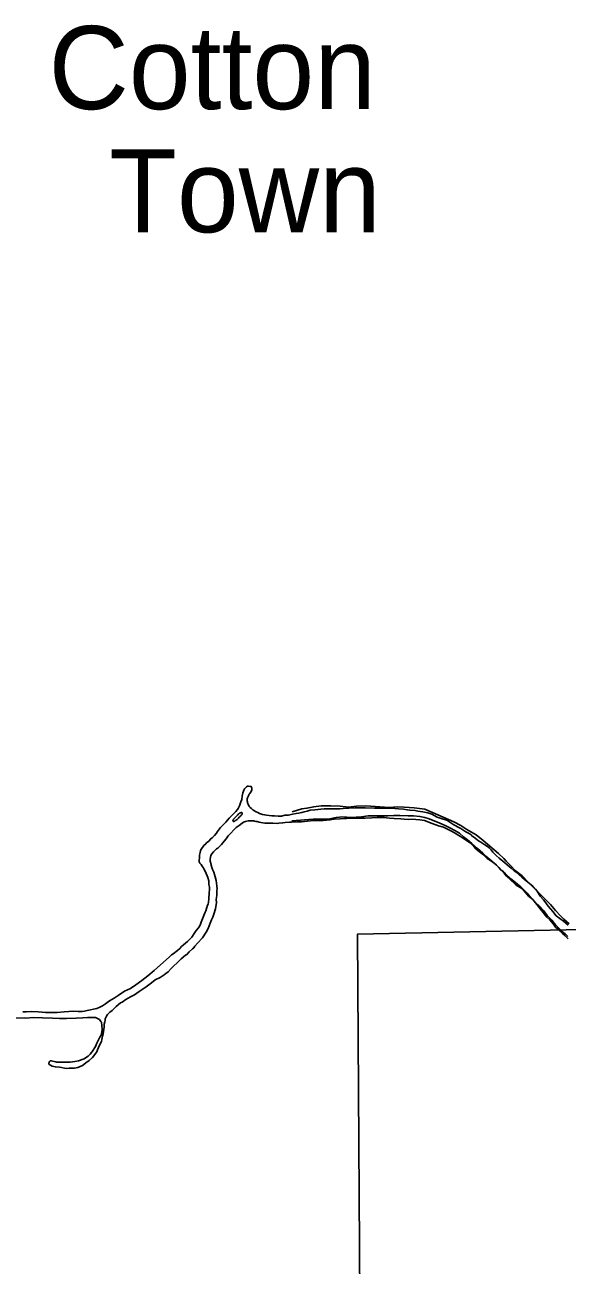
# Model space of a CAD drawing. Extents: x 1374139 to 1377472, y 1168351 to 1170484.
# Drawn here: x 1374645 to 1374679.5, y 1169664.8 to 1169743.6 of the extents above; entities that cross this region are included whole.
import ezdxf

# ---------------------------------------------------------------- set-up
doc = ezdxf.new("R2010")
doc.units = 0
doc.layers.add('Default', color=7, linetype='Continuous')

msp = doc.modelspace()

# ---------------------------------------------------------------- linework, layer by layer
at = {"layer": 'Default'}
for points in [[(1374672.64, 1169692.591), (1374672.281, 1169692.782), (1374672.151, 1169692.862), (1374671.832, 1169693.073), (1374671.602, 1169693.144), (1374671.233, 1169693.275), (1374670.894, 1169693.466), (1374670.634, 1169693.537), (1374670.425, 1169693.587), (1374670.315, 1169693.607), (1374670.006, 1169693.648), (1374669.836, 1169693.689), (1374669.496, 1169693.709), (1374669.327, 1169693.74), (1374669.097, 1169693.77), (1374668.778, 1169693.811), (1374668.528, 1169693.821), (1374668.248, 1169693.842), (1374667.849, 1169693.853), (1374667.24, 1169693.834), (1374666.661, 1169693.875), (1374666.002, 1169693.857), (1374665.253, 1169693.818), (1374665.043, 1169693.808), (1374664.763, 1169693.799), (1374664.294, 1169693.81), (1374664.044, 1169693.8), (1374663.834, 1169693.771), (1374663.455, 1169693.732), (1374663.165, 1169693.712), (1374662.965, 1169693.652), (1374662.785, 1169693.603), (1374662.626, 1169693.573), (1374662.416, 1169693.523), (1374662.266, 1169693.494), (1374662.026, 1169693.454), (1374661.776, 1169693.404), (1374661.557, 1169693.395), (1374661.337, 1169693.335), (1374661.117, 1169693.336), (1374660.888, 1169693.346), (1374660.718, 1169693.366), (1374660.388, 1169693.397), (1374660.259, 1169693.427), (1374660.129, 1169693.438), (1374659.929, 1169693.498), (1374659.829, 1169693.569), (1374659.72, 1169693.609), (1374659.57, 1169693.699), (1374659.52, 1169693.739), (1374659.421, 1169693.82), (1374659.351, 1169693.88), (1374659.291, 1169693.94), (1374659.281, 1169693.96), (1374659.241, 1169694.041), (1374659.221, 1169694.101), (1374659.172, 1169694.181), (1374659.172, 1169694.241), (1374659.162, 1169694.301), (1374659.162, 1169694.341), (1374659.152, 1169694.411), (1374659.162, 1169694.441), (1374659.172, 1169694.491), (1374659.192, 1169694.552), (1374659.213, 1169694.592), (1374659.233, 1169694.632), (1374659.263, 1169694.682), (1374659.293, 1169694.732), (1374659.323, 1169694.782), (1374659.363, 1169694.842), (1374659.403, 1169694.912), (1374659.453, 1169695.012), (1374659.453, 1169695.042), (1374659.453, 1169695.062), (1374659.443, 1169695.102), (1374659.443, 1169695.112), (1374659.423, 1169695.152), (1374659.414, 1169695.212), (1374659.234, 1169695.233), (1374659.184, 1169695.233), (1374659.114, 1169695.193), (1374659.074, 1169695.153), (1374659.024, 1169695.113), (1374658.994, 1169695.073), (1374658.954, 1169694.993), (1374658.924, 1169694.933), (1374658.873, 1169694.823), (1374658.843, 1169694.612), (1374658.813, 1169694.402), (1374658.752, 1169694.242), (1374658.712, 1169694.112), (1374658.672, 1169694.002), (1374658.592, 1169693.832), (1374658.532, 1169693.751), (1374658.442, 1169693.641), (1374658.311, 1169693.502), (1374658.191, 1169693.372), (1374658.022, 1169693.21)], [(1374662.015, 1169693.618), (1374662.634, 1169693.799), (1374662.954, 1169693.84), (1374663.383, 1169693.93), (1374663.853, 1169694.001), (1374664.472, 1169693.991), (1374665.061, 1169693.961), (1374665.6, 1169693.902), (1374666.11, 1169693.972), (1374666.689, 1169693.983), (1374667.578, 1169693.933), (1374668.187, 1169693.894), (1374668.696, 1169693.924), (1374669.126, 1169693.915), (1374669.755, 1169693.865), (1374670.434, 1169693.786), (1374671.273, 1169693.426), (1374672.282, 1169692.976), (1374672.722, 1169692.736), (1374673.112, 1169692.485), (1374673.701, 1169692.155), (1374674.151, 1169691.795), (1374674.431, 1169691.565), (1374674.841, 1169691.195), (1374675.121, 1169690.965), (1374675.46, 1169690.654), (1374675.6, 1169690.484), (1374675.9, 1169690.184), (1374676.19, 1169689.884), (1374676.62, 1169689.533), (1374677.03, 1169689.123), (1374677.26, 1169688.883), (1374677.599, 1169688.542), (1374677.809, 1169688.342), (1374678.179, 1169687.982), (1374678.429, 1169687.722), (1374678.739, 1169687.331), (1374679.059, 1169686.991), (1374679.269, 1169686.791), (1374679.619, 1169686.501)], [(1374659.614, 1169693.017), (1374659.569, 1169693.028), (1374659.479, 1169693.038), (1374659.349, 1169693.039), (1374659.229, 1169693.039), (1374659.059, 1169692.999), (1374658.929, 1169692.959), (1374658.829, 1169692.889), (1374658.639, 1169692.74), (1374658.449, 1169692.62), (1374658.319, 1169692.46), (1374658.119, 1169692.26), (1374657.939, 1169692.09), (1374657.819, 1169691.9), (1374657.698, 1169691.74), (1374657.528, 1169691.54), (1374657.288, 1169691.31), (1374657.208, 1169691.26), (1374657.088, 1169691.13), (1374657.008, 1169691.06), (1374656.918, 1169690.95), (1374656.918, 1169690.94), (1374656.857, 1169690.839)], [(1374658.022, 1169693.21), (1374657.794, 1169692.953), (1374657.518, 1169692.669)], [(1374658.499, 1169693.365), (1374658.457, 1169693.323), (1374658.426, 1169693.287), (1374658.387, 1169693.247), (1374658.349, 1169693.207), (1374658.328, 1169693.184), (1374658.318, 1169693.167), (1374658.292, 1169693.142), (1374658.284, 1169693.126), (1374658.27, 1169693.092), (1374658.259, 1169693.076), (1374658.252, 1169693.061), (1374658.25, 1169693.046), (1374658.251, 1169693.03), (1374658.258, 1169693.017), (1374658.271, 1169693.004), (1374658.288, 1169692.998), (1374658.305, 1169693), (1374658.327, 1169693.006), (1374658.353, 1169693.017), (1374658.378, 1169693.036), (1374658.4, 1169693.051), (1374658.428, 1169693.07), (1374658.455, 1169693.088), (1374658.48, 1169693.108), (1374658.512, 1169693.123), (1374658.54, 1169693.142), (1374658.565, 1169693.164), (1374658.594, 1169693.194), (1374658.615, 1169693.216), (1374658.634, 1169693.241), (1374658.656, 1169693.264), (1374658.688, 1169693.299), (1374658.721, 1169693.334), (1374658.743, 1169693.361), (1374658.768, 1169693.391), (1374658.793, 1169693.414), (1374658.815, 1169693.434), (1374658.829, 1169693.45), (1374658.839, 1169693.467), (1374658.846, 1169693.485), (1374658.847, 1169693.505), (1374658.842, 1169693.528), (1374658.832, 1169693.551), (1374658.815, 1169693.568), (1374658.796, 1169693.574), (1374658.774, 1169693.574), (1374658.751, 1169693.567), (1374658.723, 1169693.552)], [(1374658.723, 1169693.552), (1374658.673, 1169693.522), (1374658.637, 1169693.496), (1374658.596, 1169693.463), (1374658.562, 1169693.433), (1374658.539, 1169693.407), (1374658.518, 1169693.386), (1374658.499, 1169693.365)], [(1374660.386, 1169692.896), (1374660.28, 1169692.898), (1374660.147, 1169692.916), (1374660.029, 1169692.934), (1374659.921, 1169692.961), (1374659.788, 1169692.988), (1374659.697, 1169693.003), (1374659.614, 1169693.017)], [(1374665.472, 1169693.195), (1374665.341, 1169693.187), (1374665.071, 1169693.167), (1374664.672, 1169693.148), (1374664.412, 1169693.098), (1374663.973, 1169693.069), (1374663.393, 1169693.06), (1374663.184, 1169693.041), (1374662.614, 1169692.982), (1374662.325, 1169692.982), (1374661.975, 1169692.953), (1374661.845, 1169692.943), (1374661.576, 1169692.934), (1374661.406, 1169692.904), (1374661.176, 1169692.885), (1374661.056, 1169692.875), (1374660.777, 1169692.895), (1374660.487, 1169692.896), (1374660.386, 1169692.896)], [(1374661.996, 1169693.037), (1374663.354, 1169693.149), (1374664.303, 1169693.139), (1374664.812, 1169693.25), (1374665.241, 1169693.29), (1374665.771, 1169693.251), (1374666.09, 1169693.261), (1374666.42, 1169693.301), (1374666.839, 1169693.352), (1374667.329, 1169693.362), (1374667.648, 1169693.363), (1374668.098, 1169693.363), (1374668.477, 1169693.373), (1374668.847, 1169693.384), (1374669.386, 1169693.364), (1374669.715, 1169693.354), (1374670.125, 1169693.314), (1374670.445, 1169693.255), (1374670.724, 1169693.155), (1374670.974, 1169693.055), (1374671.344, 1169692.905), (1374671.773, 1169692.715), (1374672.023, 1169692.585), (1374672.343, 1169692.425), (1374672.653, 1169692.245), (1374672.902, 1169692.025), (1374673.162, 1169691.824), (1374673.432, 1169691.604), (1374673.782, 1169691.274), (1374674.122, 1169690.974), (1374674.322, 1169690.794), (1374674.572, 1169690.583), (1374674.971, 1169690.233), (1374675.231, 1169689.973), (1374675.571, 1169689.673), (1374675.911, 1169689.352), (1374676.091, 1169689.212), (1374676.331, 1169689.022), (1374676.55, 1169688.852), (1374676.95, 1169688.432), (1374677.22, 1169688.111), (1374677.47, 1169687.851), (1374677.72, 1169687.611), (1374677.97, 1169687.331), (1374678.22, 1169687.02), (1374678.51, 1169686.73), (1374678.74, 1169686.42), (1374679.19, 1169685.979), (1374679.349, 1169685.849), (1374679.529, 1169685.679)], [(1374665.472, 1169693.195), (1374666.092, 1169693.21), (1374666.644, 1169693.199), (1374667.084, 1169693.221), (1374667.404, 1169693.248), (1374667.654, 1169693.259), (1374667.867, 1169693.243)], [(1374676.147, 1169689.058), (1374675.629, 1169689.52), (1374675.529, 1169689.64), (1374675.42, 1169689.811), (1374675.28, 1169689.921), (1374675.141, 1169690.082), (1374675.001, 1169690.222), (1374674.842, 1169690.343), (1374674.603, 1169690.513), (1374674.403, 1169690.654), (1374674.164, 1169690.875), (1374674.094, 1169690.935), (1374673.915, 1169691.066), (1374673.685, 1169691.267), (1374673.556, 1169691.407), (1374673.327, 1169691.638), (1374672.968, 1169691.869), (1374672.698, 1169692.04), (1374672.329, 1169692.281), (1374672.13, 1169692.372), (1374671.621, 1169692.633), (1374671.302, 1169692.724), (1374670.913, 1169692.865), (1374670.424, 1169693.056), (1374670.114, 1169693.097), (1374669.865, 1169693.128), (1374669.685, 1169693.138), (1374669.435, 1169693.128), (1374669.136, 1169693.139), (1374668.926, 1169693.159), (1374668.497, 1169693.18), (1374668.197, 1169693.211), (1374667.997, 1169693.231), (1374667.867, 1169693.243)], [(1374657.518, 1169692.669), (1374657.471, 1169692.622), (1374657.331, 1169692.442), (1374657.27, 1169692.352), (1374657.2, 1169692.252), (1374657.08, 1169692.112), (1374656.94, 1169691.962), (1374656.84, 1169691.902), (1374656.71, 1169691.752), (1374656.58, 1169691.632), (1374656.52, 1169691.582), (1374656.41, 1169691.472), (1374656.31, 1169691.342), (1374656.239, 1169691.232), (1374656.199, 1169691.122), (1374656.179, 1169691.032), (1374656.129, 1169690.851), (1374656.129, 1169690.771), (1374656.118, 1169690.641), (1374656.098, 1169690.561), (1374656.088, 1169690.521), (1374656.098, 1169690.481), (1374656.098, 1169690.441), (1374656.148, 1169690.35), (1374656.227, 1169690.26), (1374656.297, 1169690.16), (1374656.357, 1169690.08), (1374656.406, 1169689.979), (1374656.486, 1169689.829), (1374656.615, 1169689.548), (1374656.665, 1169689.428), (1374656.714, 1169689.217), (1374656.724, 1169688.997), (1374656.754, 1169688.817), (1374656.753, 1169688.636), (1374656.743, 1169688.496), (1374656.743, 1169688.356), (1374656.722, 1169688.216), (1374656.722, 1169688.085), (1374656.702, 1169687.875), (1374656.671, 1169687.735), (1374656.641, 1169687.685), (1374656.521, 1169687.314), (1374656.49, 1169687.234), (1374656.41, 1169687.024), (1374656.36, 1169686.914), (1374656.239, 1169686.604), (1374656.169, 1169686.404), (1374656.069, 1169686.244), (1374655.919, 1169686.074), (1374655.829, 1169685.943), (1374655.638, 1169685.653), (1374655.518, 1169685.523), (1374655.368, 1169685.363), (1374655.118, 1169685.154), (1374654.978, 1169685.044), (1374654.868, 1169684.924), (1374654.728, 1169684.804), (1374654.448, 1169684.594), (1374654.358, 1169684.514), (1374654.238, 1169684.414), (1374654.227, 1169684.384)], [(1374679.537, 1169686.406), (1374679.248, 1169686.657), (1374678.789, 1169686.999), (1374678.57, 1169687.27), (1374678.281, 1169687.621), (1374678.062, 1169687.912), (1374677.983, 1169688.022), (1374677.763, 1169688.253), (1374677.574, 1169688.574), (1374677.475, 1169688.694), (1374677.295, 1169688.895), (1374677.096, 1169689.056), (1374676.887, 1169689.217), (1374676.607, 1169689.458), (1374676.239, 1169689.769), (1374676.109, 1169689.869), (1374675.93, 1169690.02), (1374675.81, 1169690.12), (1374675.531, 1169690.361), (1374675.401, 1169690.472), (1374675.162, 1169690.673), (1374674.983, 1169690.843), (1374674.763, 1169691.054), (1374674.654, 1169691.205), (1374674.524, 1169691.315), (1374674.425, 1169691.415), (1374674.255, 1169691.506), (1374673.996, 1169691.687), (1374673.846, 1169691.777), (1374673.737, 1169691.858), (1374673.527, 1169692.018), (1374673.457, 1169692.058), (1374673.378, 1169692.149), (1374673.258, 1169692.239), (1374673.039, 1169692.34), (1374672.909, 1169692.42), (1374672.739, 1169692.551), (1374672.64, 1169692.591)], [(1374656.857, 1169690.839), (1374656.829, 1169690.739), (1374656.799, 1169690.601), (1374656.81, 1169690.479), (1374656.86, 1169690.258)], [(1374656.86, 1169690.258), (1374656.876, 1169690.229), (1374656.916, 1169690.078), (1374656.976, 1169689.908), (1374657.035, 1169689.768), (1374657.114, 1169689.477), (1374657.187, 1169689.244)], [(1374657.187, 1169689.244), (1374657.217, 1169689.078), (1374657.228, 1169688.91), (1374657.241, 1169688.723)], [(1374657.241, 1169688.723), (1374657.232, 1169688.635), (1374657.232, 1169688.575), (1374657.222, 1169688.285), (1374657.181, 1169688.044), (1374657.201, 1169687.844), (1374657.15, 1169687.453), (1374657.039, 1169687.103), (1374656.969, 1169686.913), (1374656.899, 1169686.743), (1374656.809, 1169686.533), (1374656.668, 1169686.202), (1374656.548, 1169685.972), (1374656.327, 1169685.592), (1374656.007, 1169685.262), (1374655.827, 1169685.072), (1374655.757, 1169684.972), (1374655.687, 1169684.892), (1374655.476, 1169684.702), (1374655.326, 1169684.542), (1374655.246, 1169684.502), (1374654.956, 1169684.262), (1374654.856, 1169684.162), (1374654.336, 1169683.653), (1374654.136, 1169683.443), (1374653.996, 1169683.333), (1374653.885, 1169683.243), (1374653.626, 1169683.083), (1374653.306, 1169682.923), (1374653.076, 1169682.733), (1374652.735, 1169682.484), (1374652.475, 1169682.314), (1374652.295, 1169682.184), (1374651.995, 1169681.974), (1374651.735, 1169681.855), (1374651.455, 1169681.685), (1374651.205, 1169681.515), (1374651.115, 1169681.465), (1374650.835, 1169681.245), (1374650.655, 1169681.076), (1374650.575, 1169680.976), (1374650.425, 1169680.866), (1374650.285, 1169680.726), (1374650.225, 1169680.616), (1374650.145, 1169680.455), (1374650.145, 1169680.425), (1374650.128, 1169680.353)], [(1374677.388, 1169687.94), (1374677.303, 1169688.034), (1374677.024, 1169688.255), (1374676.925, 1169688.385), (1374676.845, 1169688.475), (1374676.696, 1169688.646), (1374676.626, 1169688.726), (1374676.536, 1169688.787), (1374676.317, 1169688.917), (1374676.197, 1169688.988), (1374676.147, 1169689.058)], [(1374677.388, 1169687.94), (1374677.781, 1169687.42), (1374678.186, 1169686.925)], [(1374679.555, 1169685.535), (1374679.326, 1169685.756), (1374679.186, 1169685.886), (1374679.027, 1169686.047), (1374678.748, 1169686.278), (1374678.608, 1169686.468), (1374678.389, 1169686.739), (1374678.186, 1169686.925)], [(1374700.109, 1169686.03), (1374692.682, 1169686.381), (1374666.167, 1169685.836), (1374666.331, 1169659.315), (1374639.748, 1169659.329), (1374639.928, 1169632.938), (1374613.437, 1169632.866), (1374613.711, 1169606.658), (1374612.681, 1169606.654), (1374587.094, 1169606.782), (1374586.375, 1169606.748), (1374586.378, 1169604.285)], [(1374654.227, 1169684.384), (1374653.257, 1169683.524), (1374652.837, 1169683.185), (1374652.457, 1169682.895), (1374652.087, 1169682.605), (1374651.737, 1169682.386), (1374651.367, 1169682.206), (1374650.957, 1169681.936), (1374650.697, 1169681.757), (1374650.407, 1169681.587), (1374650.147, 1169681.407), (1374649.967, 1169681.287), (1374649.787, 1169681.197), (1374649.597, 1169681.108), (1374648.997, 1169680.989), (1374648.828, 1169680.949), (1374648.668, 1169680.929), (1374648.428, 1169680.92), (1374648.128, 1169680.93), (1374647.539, 1169680.891), (1374647.09, 1169680.852), (1374646.68, 1169680.863), (1374646.341, 1169680.854), (1374646.141, 1169680.884), (1374645.872, 1169680.905), (1374645.432, 1169680.926), (1374645.113, 1169680.906), (1374644.903, 1169680.897)], [(1374649.224, 1169680.537), (1374649.016, 1169680.538), (1374648.707, 1169680.518), (1374648.297, 1169680.499), (1374647.678, 1169680.47), (1374647.239, 1169680.481), (1374646.789, 1169680.492), (1374646.15, 1169680.514), (1374645.581, 1169680.535), (1374645.092, 1169680.496), (1374644.463, 1169680.517), (1374644.063, 1169680.508), (1374643.584, 1169680.499), (1374643.045, 1169680.49), (1374642.685, 1169680.451), (1374642.002, 1169680.409)], [(1374649.224, 1169680.537), (1374649.321, 1169680.534), (1374649.446, 1169680.539), (1374649.517, 1169680.529), (1374649.598, 1169680.504), (1374649.688, 1169680.463), (1374649.766, 1169680.412), (1374649.818, 1169680.349), (1374649.867, 1169680.284), (1374649.907, 1169680.246)], [(1374649.602, 1169678.914), (1374649.662, 1169679.024), (1374649.702, 1169679.114), (1374649.803, 1169679.284), (1374649.883, 1169679.424), (1374649.933, 1169679.634), (1374649.943, 1169679.785), (1374649.924, 1169680.025), (1374649.907, 1169680.246)], [(1374650.128, 1169680.353), (1374650.11, 1169680.267), (1374650.08, 1169680.117), (1374650.064, 1169679.946), (1374650.055, 1169679.781), (1374650.028, 1169679.637), (1374650.007, 1169679.499), (1374649.966, 1169679.355), (1374649.939, 1169679.249), (1374649.92, 1169679.138), (1374649.893, 1169679.01), (1374649.833, 1169678.896)], [(1374649.833, 1169678.896), (1374649.701, 1169678.633), (1374649.641, 1169678.483), (1374649.601, 1169678.363), (1374649.34, 1169677.993), (1374649.11, 1169677.803), (1374648.91, 1169677.663), (1374648.78, 1169677.543), (1374648.69, 1169677.493), (1374648.4, 1169677.364), (1374648.181, 1169677.324), (1374647.991, 1169677.314), (1374647.841, 1169677.315), (1374647.701, 1169677.305), (1374647.542, 1169677.325), (1374647.362, 1169677.356), (1374647.242, 1169677.376), (1374646.972, 1169677.397), (1374646.763, 1169677.447), (1374646.663, 1169677.517), (1374646.583, 1169677.548), (1374646.563, 1169677.578), (1374646.563, 1169677.588), (1374646.564, 1169677.638), (1374646.574, 1169677.678)], [(1374646.798, 1169677.77), (1374646.993, 1169677.727), (1374647.063, 1169677.707), (1374647.333, 1169677.696), (1374647.452, 1169677.696), (1374647.672, 1169677.696), (1374647.912, 1169677.705), (1374648.201, 1169677.735), (1374648.451, 1169677.774), (1374648.741, 1169677.884), (1374648.791, 1169677.914), (1374648.891, 1169677.974), (1374649.051, 1169678.084), (1374649.181, 1169678.204), (1374649.261, 1169678.304), (1374649.321, 1169678.394), (1374649.522, 1169678.704), (1374649.602, 1169678.914)], [(1374646.574, 1169677.678), (1374646.576, 1169677.71), (1374646.592, 1169677.734), (1374646.617, 1169677.761), (1374646.646, 1169677.783), (1374646.668, 1169677.786), (1374646.682, 1169677.786), (1374646.709, 1169677.786), (1374646.798, 1169677.77)]]:
    msp.add_lwpolyline(points, dxfattribs=at)

# ---------------------------------------------------------------- texts
for s, p in [('Cotton', (1374646.539, 1169738.278)), ('Town', (1374650.383, 1169730.45))]:
    msp.add_text(s, height=5.28, dxfattribs=at).set_placement(p)

doc.saveas('drawing.dxf')
